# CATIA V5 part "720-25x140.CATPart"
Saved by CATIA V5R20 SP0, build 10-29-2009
Part number: 720-25x140
Definition: NONE
Nomenclature: 720-25x140
Source: Unknown
Description: 720-25x140
Bounding box of the stored display mesh (mm): x 0 to 140, y -12.5 to 12.5, z -12.5 to 12.5
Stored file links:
  C:\Users\Utente\Desktop\IO LAVORO\3D X SITO CF\X SITO\720\720-25x140.CATPart
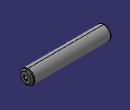
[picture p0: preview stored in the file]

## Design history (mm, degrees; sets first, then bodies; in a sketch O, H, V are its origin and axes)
Body1 "720-25x140" (main body)
  Solid1: solid without history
